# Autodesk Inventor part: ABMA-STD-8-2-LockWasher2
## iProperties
Author: Ole Germer
Shininess: 64.0
Angle Display Precision: 2
Document Length Units: 11272
Document Angle Units: 11286
Document Time Units: 11279
Document Mass Units: 11290
Document Length Units Precision: 3
Document Angle Units Precision: 2
Compacted: True
PropertySet Name: _Private Model Information
Created: 2002-11
Part Number: ABMA-STD-8-2-LockWasher2
Document SubType Name: Modeling
Designer: Ole Germer
Control State: 0
Master: False
Checked Out: False
PropertySet Name: Design Tracking Control
Density: 0.0
Volumn: 0.0
Area: 0.0
PropertySet Name: Model Information
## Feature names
1. Revolution1
2. Extrusion1
3. Circular Pattern1
4. KEY [Extrusion]
5. KEY_EXT [Extrusion]
6. FILLET1
7. KEY_EXT2 [Extrusion]
8. Fillet2
